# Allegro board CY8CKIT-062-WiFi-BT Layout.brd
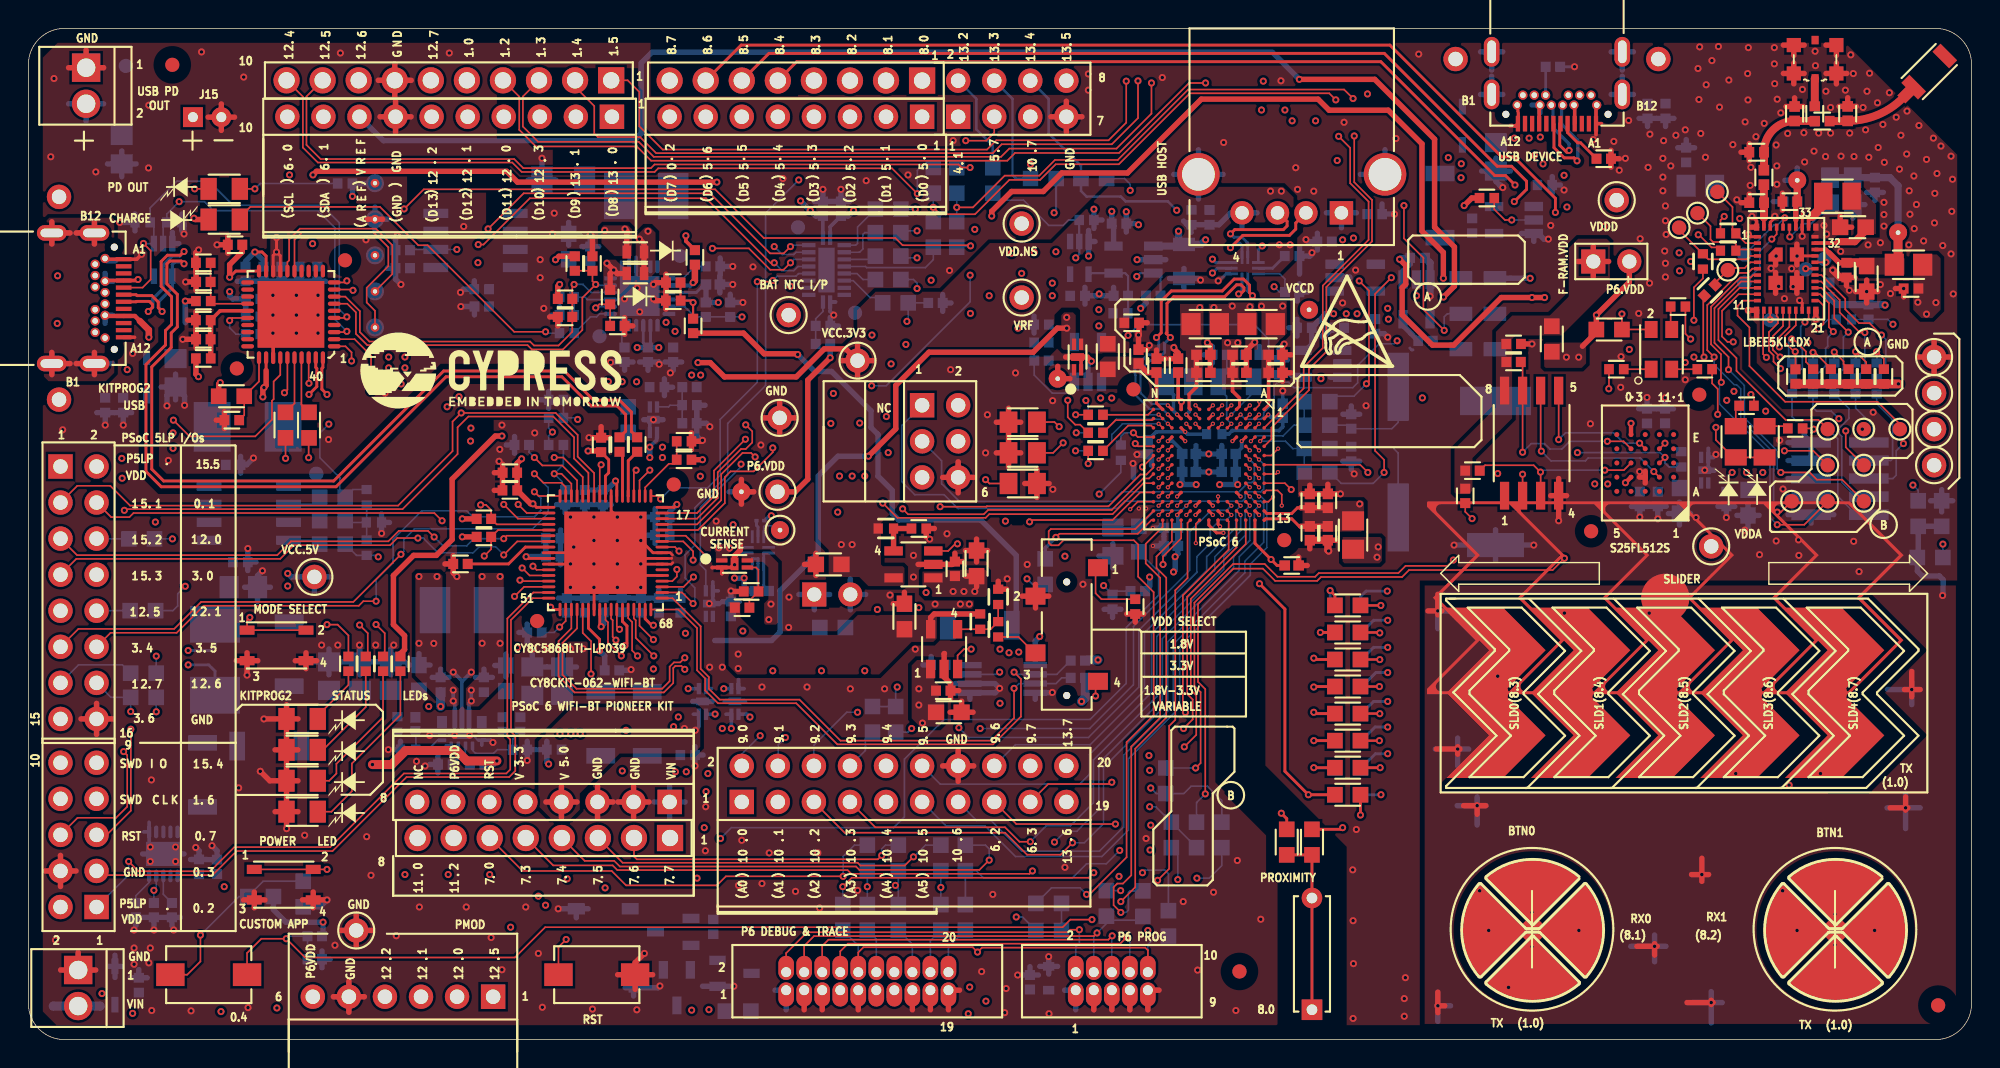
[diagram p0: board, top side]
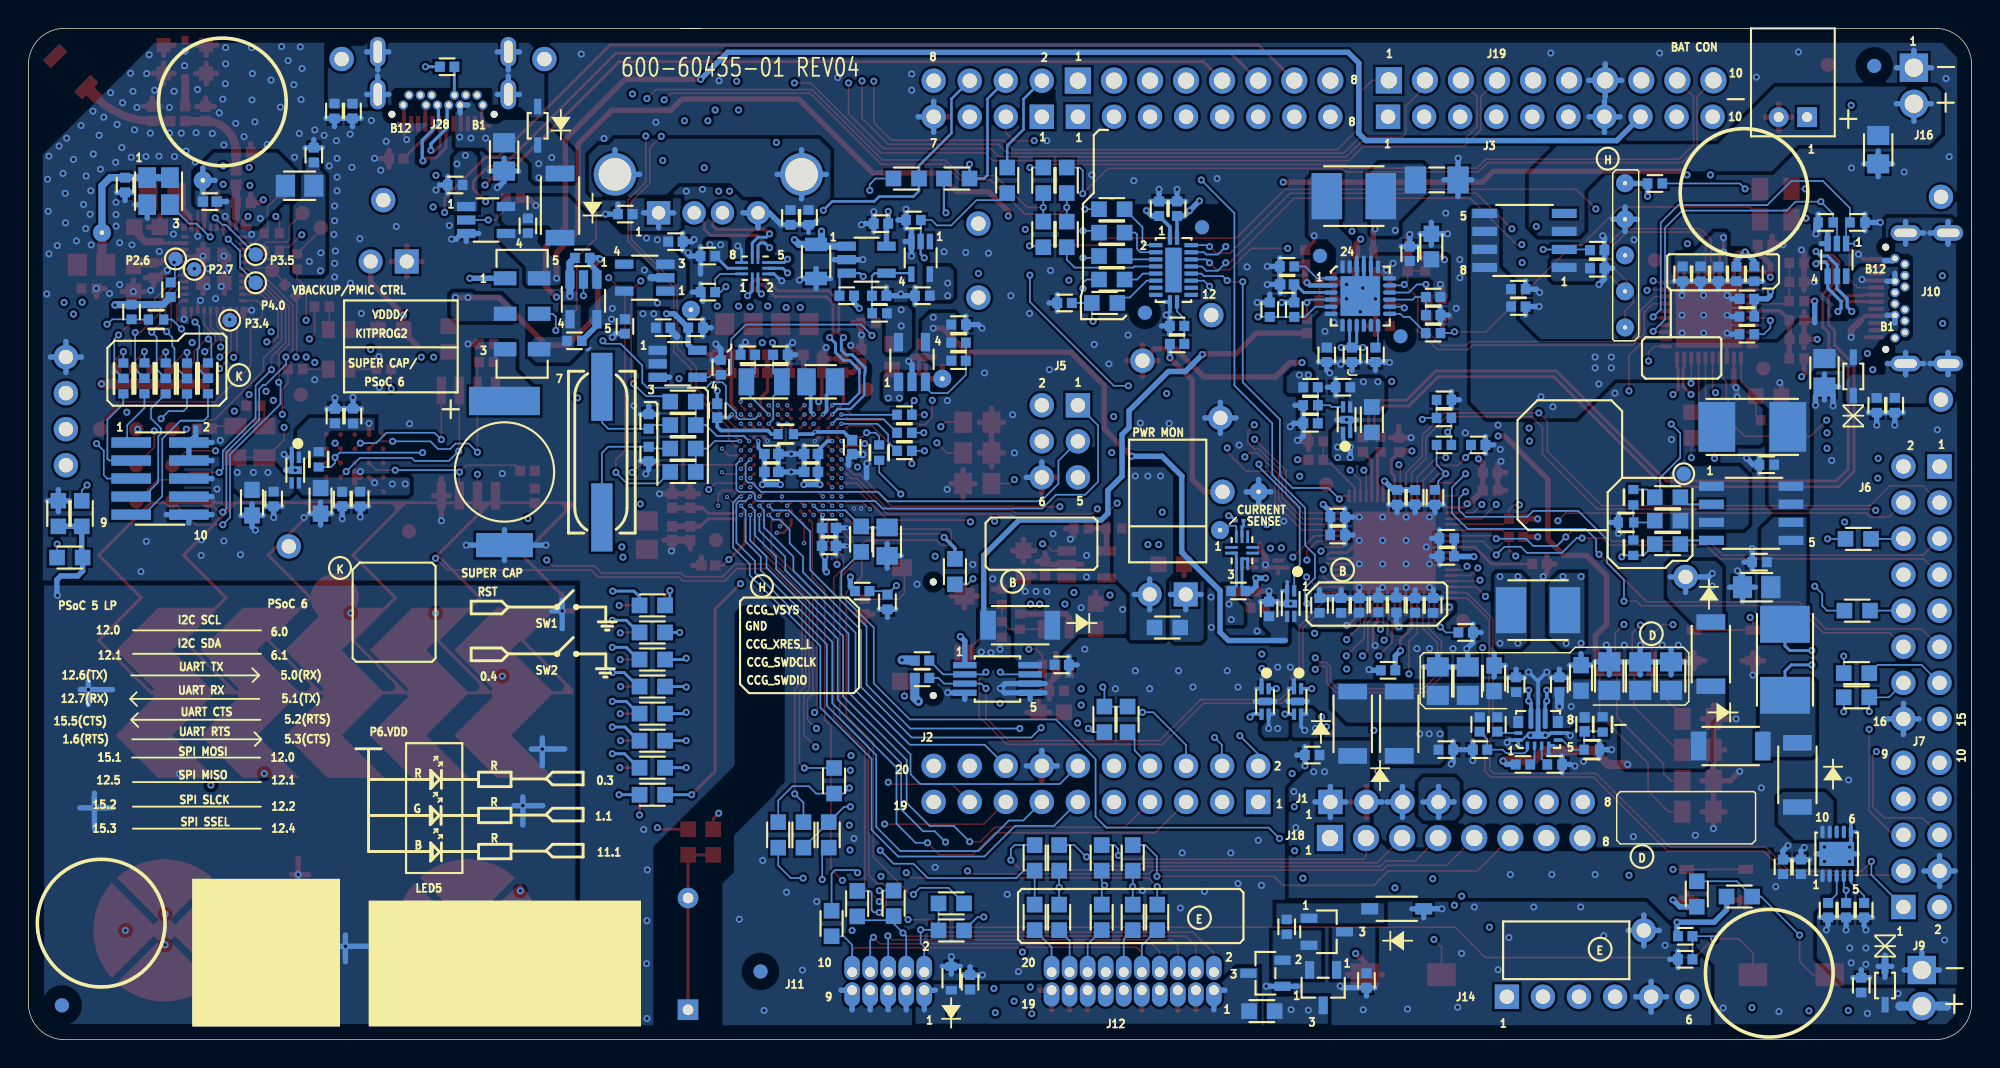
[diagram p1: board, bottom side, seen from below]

Outline 136.86 x 71.22 mm; copper layers: TOP, L02_GND, L03_SIG, L04_MIX, L05_MIX, L06_SIG, L07_GND, BOTTOM. Coordinates in mm from the lower left corner of the outline.
Outline path: 0,68.68 0,2.54 arc(0.74,0.74) 2.54,0 134.32,0 arc(136.11,0.74) 136.86,2.54 136.86,68.68 arc(136.11,70.48) 134.32,71.22 89.51,71.22 90.91,71.22 2.54,71.22 arc(0.74,70.48) 0,68.68

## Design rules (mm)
net group DP1: nets HOST_USB_DM HOST_USB_DP
net group DP2: nets DEV_USB_DM DEV_USB_DP
net group DP3: nets N17133557 N17133559
net group DP4: nets USB_DM USB_DP
net group P5LP_USB_D: nets P5LP_USB_DM P5LP_USB_DP
net group CL_CAPSEN: nets CAP_BUT0_P8_1 CAP_BUT1_P8_2 CAP_PROX_P8_0 CAP_SEG0_P8_3 CAP_SEG1_P8_4 CAP_SEG2_P8_5 CAP_SEG3_P8_6 CAP_SEG4_P8_7 CAP_TX_P1_0 J20_P8_1 J20_P8_2 J20_P8_3 J20_P8_4 J20_P8_5 J20_P8_6 J20_P8_7 P1_0 P8_1 P8_2 P8_3 P8_4 P8_5 P8_6 P8_7 P13_2 P13_3 P13_4
nets with their own width: min track width 0.559; nets ANT
nets with their own width: min track width 0.635; nets P5LP_VDD

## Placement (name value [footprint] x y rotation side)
ANT1  RFANT3216120A5T  [ANTENNA_RFANT3216120A5T]  133.87 68.18 45 top
C1  1.2 pF  [CAPC1005X61M]  128.13 65.22 270 top
C2  1.2 pF  [CAPC1005X61M]  124.39 65.21 270 top
C4  10pF  [CAPC1005X61M]  122.22 60.72 270 top
C5  0.1uF  [CAPC1005X55M_C]  124.05 59.02 180 top
C7  4.7uF  [CAPC1608X90M]  128.5 57.22 180 top
C8  1uF  [CAPC1005X55M_D]  14.55 55.98 180 top
C9  1uF  [CAPC1005X55M_D]  46.94 55.09 270 top
C10  0.1uF  [CAPC1005X55M_C]  12.32 54.71 180 top
C11  0.1uF  [CAPC1005X55M_C]  128.04 54.2 270 top
C12  4.7uF  [CAPC1608X90M]  129.46 53.59 270 top
C13  0.1uF  [CAPC1005X55M_C]  132.59 52.9 180 top
C14  0.1uF  [CAPC1005X55M_C]  45.42 52.04 180 top
C15  0.1uF  [CAPC1005X55M_C]  12.32 50.67 180 top
C16  0.1uF  [CAPC1005X55M_C]  77.7 50.49 180 top
C17  0.1uF  [CAPC1005X55M_C]  104.6 49 0 top
C18  0.1uF  [CAPC1005X55M]  82.75 48.23 0 top
C19  1uF  [CAPC1005X55M]  85.29 48.23 0 top
C20  0.1uF  [CAPC1005X55M]  87.83 48.23 0 top
C21  1uF  [CAPC1005X55M]  78.18 48.11 90 top
C22  0.1uF  [CAPC1005X55M]  79.45 47.47 90 top
C23  4.7uF  [CAPC1005X55M]  80.98 47.47 90 top
C24  10uF  [CAPC1005X55M]  82.75 46.96 0 top
C25  0.1uF  [CAPC1005X55M]  85.29 46.96 0 top
C26  1uF  [CAPC1005X55M]  87.83 46.96 0 top
C27  2.2nF  [CAPC2012X70M]  76.38 35.07 90 bottom
C28  0.1uF  [CAPC1005X55M_C]  14.33 43.63 180 top
C29  10nF  [CAPC2012X95M_A]  70.03 43.48 180 top
C30  1uF  [CAPC1005X55M_D]  40.34 41.88 270 top
C31  0.47nF  [CAPC2012X70M]  70.03 41.33 180 top
C32  1uF  [CAPC1005X55M_D]  33.91 39.93 180 top
C33  0.47nF  [CAPC2012X70M]  70.03 39.17 180 top
C34  0.1uF  [CAPC1005X55M_C]  33.91 38.68 180 top
C35  0.1uF  [CAPC1005X55M]  90.25 37.95 90 top
C36  1uF  [CAPC1005X55M]  91.52 37.95 90 top
C37  1uF  [CAPC1005X55M]  90.25 35.66 270 top
C38  0.1uF  [CAPC1005X55M]  91.52 35.66 270 top
C39  4.7uF  [CAPC1608X90M]  66.78 33.55 90 top
C40  1uF  [CAPC1005X55M_D]  30.43 33.5 180 top
C41  4.7uF  [CAPC1608X90M]  56.36 33.47 180 top
C42  1uF  [CAPC1005X55M]  88.97 33.39 0 top
C43  0.1uF  [CAPC1005X55M_D]  65.25 33.16 90 top
C44  0.1uF  [CAPC1005X55M_C]  50.9 31.56 0 top
C45  4.7uF  [CAPC1608X90M]  61.7 29.8 90 top
C46  0.1uF  [CAPC1005X55M_D]  64.43 24.58 0 top
C47  4.7uF  [CAPC1608X90M]  64.82 23.06 0 top
C48  10nF  [CAPC1005X55M_C]  114.03 65.41 270 bottom
C49  10uF  [CAPC2012X140M]  6.58 62.68 270 bottom
C50  0.1uF  [CAPC1005X55M_C]  116.75 62.3 90 bottom
C51  10uF  [CAPC2012X140M]  103.35 62.17 270 bottom
C52  22uF  [CAPC3216X180M_A]  37.67 60.55 180 bottom
C53  0.1uF  [CAPC1005X55M_C]  130.05 60.19 270 bottom
C54  2.2uF  [CAPC1005X55M]  124.08 59.02 180 bottom
C55  1uF  [CAPC1005X55M_D]  57.23 58.52 90 bottom
C56  1uF  [CAPC1005X55M_D]  55.96 58.52 270 bottom
C57  0.1uF  [CAPC1005X55M_C]  94.82 58.14 0 bottom
C58  10nF  [CAPC1005X55M_C]  83.18 57.91 270 bottom
C59  0.39nF  [CAPC1005X55M_B]  10.28 57.56 0 bottom
C60  0.39nF  [CAPC1005X55M_B]  8.04 57.56 180 bottom
C61  1uF  [CAPC1005X55M_D]  76.81 57.47 180 bottom
C62  1uF  [CAPC1005X55M_D]  91.29 56.2 0 bottom
C63  4.7uF  [CAPC1608X90M]  38.05 55.85 90 bottom
C64  0.1uF  [CAPC1005X55M_D]  39.57 55.35 90 bottom
C65  10nF  [CAPC1005X55M_C]  89 55.19 0 bottom
C66  10uF  [CAPC2012X100M]  81.38 54.81 270 bottom
C67  1uF  [CAPC1005X55M_D]  48.21 54.46 0 bottom
C68  0.1uF  [CAPC1005X55M_C]  20.35 53.93 270 bottom
C69  0.1uF  [CAPC1005X55M_C]  19.09 53.93 270 bottom
C70  1uF  [CAPC1005X55M_D]  17.83 53.93 270 bottom
C71  1uF  [CAPC1005X55M_D]  16.56 53.93 270 bottom
C72  0.1uF  [CAPC1005X55M_C]  15.3 53.93 270 bottom
C73  2.2uF  [CAPC1005X55M]  48.21 53.19 0 bottom
C74  10nF  [CAPC1005X55M_C]  31.92 52.86 0 bottom
C75  1uF  [CAPC1005X55M_D]  76.94 52.39 180 bottom
C76  0.1uF  [CAPC1005X55M_C]  73.89 52.39 180 bottom
C77  1uF  [CAPC1005X55M_D]  15.82 52.17 0 bottom
C78  1uF  [CAPC1005X55M_D]  31.92 51.64 0 bottom
C79  0.1uF  [CAPC1005X55M_C]  15.82 50.93 0 bottom
C80  0.1uF  [CAPC1005X55M_C]  71.35 50.36 0 bottom
C81  1uF  [CAPC1005X55M_D]  94.84 50.23 90 bottom
C82  0.1uF  [CAPC1005X55M_C]  89.87 50.14 0 bottom
C83  0.1uF  [CAPC1005X55M_C]  15.82 49.68 0 bottom
C84  0.1uF  [CAPC1005X55M_C]  71.35 49.09 0 bottom
C85  33pF  [CAPC1005X55M_D]  86.18 48.23 0 bottom
C86  18pF  [CAPC1005X55M_D]  83.9 48.23 180 bottom
C87  10uF  [CAPC1005X55M_D]  45.42 48.23 270 bottom
C88  1uF  [CAPC1005X55M_D]  43.64 48.23 270 bottom
C89  10uF  [CAPC2012X140M]  10.36 46.96 270 bottom
C90  0.1uF  [CAPC1005X55M_C]  44.27 45.95 180 bottom
C91  0.1uF  [CAPC1005X55M_C]  46.56 44.68 0 bottom
C92  10nF  [CAPC1005X55M_C]  5.41 44.68 270 bottom
C93  1uF  [CAPC1005X55M]  88.34 44.3 90 bottom
C94  1uF  [CAPC1005X55M_D]  115.27 43.92 90 bottom
C95  0.1uF  [CAPC1005X55M_C]  114 43.92 90 bottom
C96  12pF  [CAPC1005X55M_D]  93.17 43.54 90 bottom
C97  1uF  [CAPC1005X55M_D]  34.75 41.88 180 bottom
C98  4.7uF  [CAPC1005X55M]  78.84 41.72 270 bottom
C99  12pF  [CAPC1005X55M_D]  93.17 41.25 270 bottom
C100  1uF  [CAPC1005X55M]  84.53 41.25 180 bottom
C101  1uF  [CAPC1005X55M]  81.74 41.25 0 bottom
C102  0.1uF  [CAPC1005X55M_C]  14.43 40.49 180 bottom
C103  0.33F  [CAP_DSK-3R3H334T-HL]  103.33 39.98 180 bottom
C104  0.1uF  [CAPC1005X55M]  84.53 39.98 180 bottom
C105  0.1uF  [CAPC1005X55M]  81.74 39.98 0 bottom
C106  0.1uF  [CAPC1005X55M_C]  40.46 38.2 270 bottom
C107  1uF  [CAPC1005X55M_D]  39.19 38.2 270 bottom
C108  0.1uF  [CAPC1005X55M_C]  119.58 38.07 270 bottom
C109  1uF  [CAPC1005X55M_D]  114.76 38.07 270 bottom
C110  0.1uF  [CAPC1005X55M_C]  113.49 38.07 270 bottom
C111  22uF  [CAPC1608X90M]  116.28 37.95 270 bottom
C112  22uF  [CAPC1608X90M]  121.11 37.82 270 bottom
C113  1uF  [CAPC1005X55M_D]  44.65 36.8 180 bottom
C114  1uF  [CAPC1005X55M]  80.47 36.04 180 bottom
C115  0.1uF  [CAPC1005X55M_C]  44.65 35.53 180 bottom
C116  0.1uF  [CAPC1005X55M_C]  36.96 35.31 0 bottom
C117  0.1uF  [CAPC1005X55M]  80.47 34.77 180 bottom
C118  1uF  [CAPC1005X55M_D]  36.96 34.04 0 bottom
C119  0.1uF  [CAPC1005X55M_C]  14.94 33.63 180 bottom
C120  22uF  [CAPC2012X140M]  15.14 31.87 0 bottom
C121  0.1uF  [CAPC1005X55M_C]  76.35 30.83 270 bottom
C122  1uF  [CAPC1005X55M_D]  41.78 30.61 90 bottom
C123  0.1uF  [CAPC1005X55M_C]  40.51 30.61 90 bottom
C124  0.1uF  [CAPC1005X55M_C]  45.92 30.58 90 bottom
C125  0.1uF  [CAPC1005X55M_C]  44.4 30.58 90 bottom
C126  1uF  [CAPC1005X55M_D]  43.13 30.58 90 bottom
C127  1uF  [CAPC1005X55M_D]  39.19 30.58 90 bottom
C128  0.1uF  [CAPC1005X55M_C]  37.92 30.58 90 bottom
C129  0.1uF  [CAPC1005X55M_C]  49.48 30.33 90 bottom
C130  1uF  [CAPC1005X55M_D]  35.64 28.68 180 bottom
C131  0.1uF  [CAPC1005X55M_D]  64.08 26.39 180 bottom
C132  1uF  [CAPC1005X55M_D]  41.1 26.01 0 bottom
C133  22uF  [CAPC2012X140M]  25.52 25.6 90 bottom
C134  22uF  [CAPC2012X140M]  23.34 25.6 90 bottom
C135  22uF  [CAPC2012X140M]  21.17 25.6 90 bottom
C136  10uF  [CAPC1608X90M]  27.51 25.48 90 bottom
C137  10uF  [CAPC1608X90M]  33.63 25.45 90 bottom
C138  10uF  [CAPC2012X140M]  37.59 25.25 90 bottom
C139  10uF  [CAPC2012X140M]  35.48 25.25 90 bottom
C140  0.1uF  [CAPC1005X55M_C]  32.08 24.99 270 bottom
C141  0.1uF  [CAPC1005X55M_C]  29.03 24.99 270 bottom
C142  22pF  [CAPC1005X55M]  27.25 22.2 270 bottom
C143  0.1uF  [CAPC1005X55M_C]  29.36 19.38 0 bottom
C144  1uF  [CAPC1005X55M_D]  13.28 12.17 270 bottom
C145  10nF  [CAPC1005X55M_C]  12.01 12.17 270 bottom
C146  1uF  [CAPC1005X55M_D]  10.11 9.12 90 bottom
C147  1uF  [CAPC1005X55M_D]  70.54 4.04 90 bottom
C148  1uF  [CAPC1005X55M_C]  7.77 3.84 270 bottom
CAP_SH1  CAP_SHIELD  [CAP_SH1]  134.59 30.8 0 top
CSB1  Button 1  [CSB_10MM_3SEG]  105.94 7.7 270 top
CSB2  Button 2  [CSB_10MM_3SEG]  127.27 7.7 90 top
CSS1  Slider  [CSS_L5S_4X12_1P4_MUTUAL_CYPS]  115.28 24.42 0 top
D1  RB551SS-30T2R  [DIO160X80X63-2M]  42.75 55.47 180 top
D2  RB551SS-30T2R  [DIO160X80X63-2M]  42.75 53.95 180 top
D3  PMEG3020BEP  [SODFL4725X110M]  99.42 58.74 90 bottom
D4  PMEG3020BEP  [SODFL4725X110M]  67.01 29.18 0 bottom
D5  PMEG3020BEP  [SODFL4725X110M]  18.36 27.15 270 bottom
D6  PMEG3020BEP  [SODFL4725X110M]  40.31 22.25 270 bottom
D7  PMEG3020BEP  [SODFL4725X110M]  43.59 22.24 270 bottom
D8  PMEG3020BEP  [SODFL4725X110M]  16.97 20.68 0 bottom
D9  PMEG3020BEP  [SODFL4725X110M]  12.27 18.64 270 bottom
D10  BZT52C3V9-7-F  [SOD3715X145M]  40.49 9.21 0 bottom
J1  CON8  [SULLINS_PPPC081LFBN-RC]  45.16 16.74 180 top
J2  CON 10x2  [SULLINS_PPPC102LFBN-R_FLIP]  50.24 16.74 0 top
J3  CON10  [SULLINS_PPPC101LFBN-RC]  41.1 65 180 top
J4  CON8  [SULLINS_PPPC081LFBN-RC]  62.94 65 180 top
J5  HDR 3x2  [SULLINS_PPPC032LFBN-RC_FLIP]  62.94 44.68 270 top
J6  CON 8x2  [SULLINS_PPPC082LFBN-R_FLIP]  2.26 40.37 270 top
J7  CON 5x2  [SULLINS_PPPC052LFBN-RC_FLIP]  4.8 9.34 90 top
J8  2-pin R/A HDR  [HARWIN_M20-9960245]  55.35 31.35 0 bottom
J9  OSTVN02A150  [OST_OSTVN02A150]  3.51 4.9 270 top
J10  USB TYPE-C  [JAE_DX07S024XJ1R1100]  6.71 54.97 270 top
J11  HDR_S 5x2  [CNC_3220-10-0100-00]  73.76 3.48 0 top
J12  HDR_S 10x2  [CNCTECH_3220-20-0100-00]  53.37 3.48 0 top
J13  CON 2x1  [SAMTEC_BCS-101-L-S-HE]  90.4 2.1 0 top
J14  CON 6x1  [SULLINS_PPPC061LGBN-RC_FLIP]  32.73 3.02 0 top
J15  HDR_S 2x1_R/A  [JST_S2B-PH-K-S]  11.59 64.97 0 bottom
J16  OSTVN02A150  [OST_OSTVN02A150]  4.06 68.45 270 top
J18  HEADER 8  [SULLINS_PBC08SAAN]  45.19 14.2 180 top
J19  HEADER 10  [SULLINS_PBC10SAAN]  41.04 67.56 180 top
J20  HEADER 8  [SULLINS_PBC08SAAN]  62.94 67.55 180 top
J21  CON 4x2  [SULLINS_PPPC042LFBN-RC_FLIP]  65.48 67.54 0 top
J25  50MIL KEYED SMD  [SAMTEC_FTSH-105-01-L-DV-K]  129.62 42.05 270 bottom
J26  HDR 2x1  [3M_961102-6404-AR]  110.21 54.81 0 top
J27  0676433911  [MOLEX_676433911]  92.47 58.23 180 top
J28  DX07S024XJ1R1100  [JAE_DX07S024XJ1R1100]  110.4 64.51 180 top
J29  MM8430-2610RB3  [RF_SW_MUR_MM8430-2610B]  125.83 69.05 180 top
L1  6.8nH  [INDC1005X60M]  126.33 64.69 180 top
L2  2.2uH  [INDC2016X100M]  127.41 59.4 0 top
L3  1K @ 100MHz  [INDC2012X105M]  132.41 54.58 180 top
L4  1K @ 100MHz  [INDC2012X105M]  82.88 50.39 180 top
L5  1K @ 100MHz  [INDC2012X105M]  86.82 50.39 0 top
L6  1K @ 100MHz  [INDC2012X105M]  93.29 35.53 90 top
L7  1K @ 100MHz  [INDC2012X105M]  117.75 60.14 0 bottom
L8  1.5uH  [INDM4242X200M]  43.51 59.41 180 bottom
L9  2.2uH  [INDC2016X100M]  81.05 46.33 180 bottom
L10  1.5uH  [INDM4242X200M]  30.54 30.25 180 bottom
L11  6.8nH  [INDC1005X60M]  121.72 58.95 180 top
L12  6.8nH  [INDC1005X60M]  121.72 62.5 180 top
L13  6.8nH  [INDC1005X60M]  125.81 65.21 270 top
LED1  RED LED  [LEDC2012X120M]  19.28 18.23 180 top
LED2  AMBER LED  [LEDC2012X120M]  19.28 22.59 180 top
LED3  GREEN LED  [LEDC2012X120M]  19.28 20.41 180 top
LED4  AMBER LED  [LEDC2012X120M]  19.28 16.05 180 top
LED5  RGB LED  [LED_AAA3528LSEEZGKQBKS]  115.01 48.62 270 top
LED6  RED LED  [LEDC2012X120M]  13.79 57.76 0 top
LED7  GREEN LED  [LEDC2012X120M]  13.79 59.92 180 top
LED8  ORANGE LED  [LEDC2012X120M]  120.24 42.11 90 top
LED9  RED LED  [LEDC2012X120M]  122.28 42.11 90 top
NOREF  -  [unnamed]  2.16 45.08 0 top
NOREF#2  -  [#2]  140.67 111.58 0 top
NOREF#3  -  [#2]  -288.85 -207.67 0 top
NOREF#4  -  [unnamed#3]  10.13 68.66 0 top
NOREF#5  -  [unnamed#3]  85.29 4.8 0 top
NOREF#6  -  [unnamed]  114.79 69.06 270 top
NOREF#7  -  [unnamed#3]  134.5 2.41 0 top
NOREF#8  -  [#2]  0 4.22 0 top
NOREF#9  -  [#2]  130.83 0 90 top
NOREF#10  -  [#2]  39.6 25.37 0 top
NOREF#11  -  [#2]  39.6 23.73 0 top
NOREF#12  -  [unnamed]  100.51 69.06 270 top
NOREF#13  -  [#2]  5.28 0 90 top
NOREF#14  -  [#2]  122.89 73.48 0 top
NOREF#15  -  [#2]  135.98 0.62 0 top
NOREF#16  -  [#2]  0 66.56 0 top
NOREF#17  -  [#2]  32.43 47.14 0 top
NOREF#18  -  [unnamed]  2.16 59.36 0 top
NOREF#19  -  [#2]  17.48 -23.04 0 top
NOREF#20  -  [unnamed#3]  134.5 2.41 180 bottom
NOREF#21  -  [#2]  99.35 64.54 90 bottom
NOREF#22  -  [unnamed#3]  6.86 68.58 180 bottom
NOREF#23  -  [#2]  86.84 68.4 180 bottom
NOREF#24  -  [#2]  71.87 1.98 90 bottom
NOREF#25  -  [#2]  103.3 5.36 180 bottom
NOREF#26  -  [#2]  120.12 6.12 180 bottom
NOREF#27  -  [unnamed#3]  85.29 4.8 180 bottom
Q1  AO4838  [SOIC127P600X175-8M]  15.52 37.07 180 bottom
Q2  PMV48XP,215  [SOT95P230X110-3M]  45.42 7.59 270 bottom
Q3  DMP3098L-7  [SOT92P240X110-3M]  49.73 4.67 90 bottom
Q4  NTR4171PT1G  [SOT95P237X111-3M_A]  45.67 3.66 0 bottom
R1  10K  [RESC1005X40M_A]  38.48 54.66 90 top
R2  10K  [RESC1005X40M_A]  39.73 54.66 90 top
R3  75K  [RESC1005X40M_A]  12.32 53.36 0 top
R4  10K  [RESC1005X40M_A]  45.42 53.31 0 top
R5  10K  [RESC1005X40M_A]  40.97 52.3 90 top
R6  10K  [RESC1005X40M_A]  37.8 52.17 180 top
R7  120K  [RESC1005X40M_B]  12.32 52.02 0 top
R8  330ohm  [RESC1005X40M_B]  116.18 51.63 0 top
R9  10K  [RESC1005X40M_A]  37.8 50.9 180 top
R10  10K  [RESC1005X40M_A]  41.48 50.27 0 top
R11  10K  [RESC1005X40M_A]  46.81 50.27 90 top
R12  0ohm  [RESC1608X55M_A]  111.33 50.01 0 top
R13  0ohm  [RESC1608X55M_A]  107.29 49.34 90 top
R14  75K  [RESC1005X40M_A]  12.32 49.32 0 top
R15  0ohm  [RESC1608X55M_A]  76.02 48.11 270 top
R16  120K  [RESC1005X40M_B]  12.32 47.98 0 top
R17  10K  [RESC1005X40M_A]  104.6 47.73 180 top
R18  750ohm  [RESC1005X40M_B]  111.84 47.22 0 top
R19  270ohm  [RESC1005X40M_B]  118.06 47.22 0 top
R20  10K  [RESC1005X40M_A]  124.45 46.7 270 top
R21  49.9K  [RESC1005X40M_B]  125.7 46.7 90 top
R22  49.9K  [RESC1005X40M_B]  126.94 46.7 90 top
R23  49.9K  [RESC1005X40M_B]  128.19 46.7 90 top
R24  49.9K  [RESC1005X40M_B]  129.43 46.7 90 top
R25  49.9K  [RESC1005X40M_B]  130.68 46.7 90 top
R26  0ohm  [RESC1608X55M_A]  14.3 45.31 0 top
R27  1K  [RESC1005X40M_B]  121.01 44.65 180 top
R28  33OHM  [RESC1005X40M_B]  75.16 44.01 180 top
R29  0ohm  [RESC1608X55M_A]  18.11 43.28 90 top
R30  0ohm  [RESC1608X55M_A]  19.76 43.28 90 top
R31  100ohm  [RESC1005X40M_B]  124.43 43.05 180 top
R32  33OHM  [RESC1005X40M_B]  75.16 42.74 180 top
R33  30K  [RESC1005X40M_B]  46.18 42.14 180 top
R34  22ohm  [RESC1005X40M_A]  41.63 41.91 270 top
R35  22ohm  [RESC1005X40M_A]  42.88 41.91 270 top
R36  33OHM  [RESC1005X40M_B]  75.16 41.47 180 top
R37  15K  [RESC1005X40M_B]  46.18 40.84 180 top
R38  10K  [RESC1005X40M_A]  101.7 40.07 180 top
R39  10K  [RESC1005X40M_A]  101.19 38.3 270 top
R40  4.7K  [RESC1005X40M_A]  32.08 36.68 180 top
R41  158K  [RESC1005X40M]  60.39 36 180 top
R42  49.9K  [RESC1005X40M_B]  62.71 36 180 top
R43  4.7K  [RESC1005X40M_A]  32.08 35.41 180 top
R44  0ohm  [RESC1608X55M_A]  134.75 37.05 90 bottom
R45  0ohm  [RESC1608X55M_A]  133.1 37.05 90 bottom
R46  160K  [RESC1005X40M]  68.3 31.18 270 top
R47  560ohm  [RESC1608X55M_A]  92.91 30.58 180 top
R48  49.9K  [RESC1005X40M_B]  77.95 30.5 270 top
R49  10K  [RESC1005X40M_A]  50.27 30.42 0 top
R50  62K  [RESC1005X40M]  67.03 29.44 90 top
R51  22.6K  [RESC1005X40M]  68.3 28.9 90 top
R52  560ohm  [RESC1608X55M_A]  92.91 28.68 180 top
R53  560ohm  [RESC1608X55M_A]  92.91 26.77 180 top
R54  750ohm  [RESC1005X40M_B]  22.54 26.47 270 top
R55  750ohm  [RESC1005X40M_B]  23.76 26.47 270 top
R56  750ohm  [RESC1005X40M_B]  24.98 26.47 270 top
R57  390ohm  [RESC1005X40M_B]  26.2 26.47 270 top
R58  560ohm  [RESC1608X55M_A]  92.91 24.87 180 top
R59  560ohm  [RESC1608X55M_A]  92.91 22.96 180 top
R60  560ohm  [RESC1608X55M_A]  92.91 21.06 180 top
R61  560ohm  [RESC1608X55M_A]  92.91 19.15 180 top
R62  0ohm  [RESC1608X55M_A]  92.91 17.25 0 top
R63  560ohm  [RESC1608X55M_A]  88.62 13.91 90 top
R64  0ohm  [RESC1608X55M_A]  90.4 13.91 90 top
R65  0ohm  [RESC1608X55M_A]  19.35 10.25 270 bottom
R66  0ohm  [RESC1608X55M_A]  16.36 10.08 180 bottom
R67  10K  [RESC1005X40M_A]  20.17 7.28 0 bottom
R68  10K  [RESC1005X40M_A]  20.17 5.66 180 bottom
R69  100K  [RESC1005X40M_B]  115.3 65.41 270 bottom
R70  0ohm  [RESC1608X55M_A]  75.03 60.65 0 bottom
R71  0ohm  [RESC1608X55M_A]  71.48 60.65 0 bottom
R72  0ohm  [RESC1608X55M_A]  67.92 60.52 90 bottom
R73  0ohm  [RESC1608X55M_A]  65.38 60.52 90 bottom
R74  0ohm  [RESC1608X55M_A]  63.73 60.52 90 bottom
R75  750ohm  [RESC1005X40M_B]  22.3 60.3 180 bottom
R76  100K  [RESC1005X40M_B]  106.8 60.19 180 bottom
R77  0ohm  [RESC1608X55M_A]  60.55 58.49 180 bottom
R78  100K  [RESC1005X40M_B]  81.91 57.91 270 bottom
R79  100K  [RESC1005X40M_B]  74.52 57.73 0 bottom
R80  100K  [RESC1005X40M_B]  101.68 57.32 90 bottom
R81  0ohm  [RESC1608X55M_A]  60.55 56.84 180 bottom
R82  0ohm  [RESC1608X55M_A]  65.38 56.71 270 bottom
R83  0ohm  [RESC1608X55M_A]  63.73 56.71 270 bottom
R84  10K  [RESC1005X40M_A]  26.37 55.6 0 bottom
R85  0ohm  [RESC1608X55M_A]  60.55 55.19 180 bottom
R86  1M  [RESC1005X40M_B]  97.84 55.06 180 bottom
R87  150ohm  [RESC1005X40M_A]  26.37 54.33 180 bottom
R88  0ohm  [RESC1608X55M_A]  60.55 53.54 180 bottom
R89  10K  [RESC1005X40M_A]  126.84 52.82 270 bottom
R90  100K  [RESC1005X40M_A]  89 52.65 180 bottom
R91  10K  [RESC1005X40M_A]  79.22 52.39 0 bottom
R92  26.7K  [RESC1005X40M_A]  37.92 52.3 180 bottom
R93  0ohm  [RESC1608X55M_A]  61.06 51.88 180 bottom
R94  12.4K  [RESC1005X40M_A]  49.43 51.41 270 bottom
R95  10K  [RESC1005X40M_A]  47.7 51.41 90 bottom
R96  49.9K  [RESC1005X40M_B]  129.59 51.25 270 bottom
R97  100K  [RESC1005X40M_B]  76.91 51.16 0 bottom
R98  10K  [RESC1005X40M_A]  37.92 51.03 0 bottom
R99  0ohm  [RESC1005X40M]  127.86 50.72 180 bottom
R100  10K  [RESC1005X40M_A]  55.96 50.27 0 bottom
R101  100K  [RESC1005X40M_A]  92.15 50.14 0 bottom
R102  750ohm  [RESC1005X40M_B]  37.92 49.76 180 bottom
R103  100K  [RESC1005X40M_B]  98.4 49.22 180 bottom
R104  10K  [RESC1005X40M_A]  55.96 49 180 bottom
R105  400ohm  [RESC1005X40M_A]  41.99 48.23 270 bottom
R106  120K  [RESC1005X40M_A]  71.35 47.82 0 bottom
R107  100K  [RESC1005X40M_B]  88.09 47.35 90 bottom
R108  0ohm  [RESC1005X40M]  124.21 47.12 270 bottom
R109  0ohm  [RESC1005X40M]  128.68 47.12 270 bottom
R110  0ohm  [RESC1005X40M]  127.18 47.12 270 bottom
R111  0ohm  [RESC1005X40M]  130.17 47.11 270 bottom
R112  0ohm  [RESC1005X40M]  125.68 47.11 270 bottom
R113  0ohm  [RESC1005X40M]  124.21 46.03 270 bottom
R114  0ohm  [RESC1005X40M]  128.68 46.03 270 bottom
R115  0ohm  [RESC1005X40M]  127.18 46.02 270 bottom
R116  0ohm  [RESC1005X40M]  130.17 46.02 270 bottom
R117  0ohm  [RESC1005X40M]  125.68 46.02 270 bottom
R118  120K  [RESC1005X40M_A]  46.56 45.95 180 bottom
R119  49.9K  [RESC1005X40M_B]  37.16 45.06 0 bottom
R120  0ohm  [RESC1608X55M_A]  90.75 44.93 0 bottom
R121  100K  [RESC1005X40M_B]  6.68 44.68 270 bottom
R122  33OHM  [RESC1005X40M_B]  75.16 44.01 180 bottom
R123  49.9K  [RESC1005X40M_B]  37.16 43.79 180 bottom
R124  0ohm  [RESC1608X55M_A]  42.24 43.66 270 bottom
R125  75K  [RESC1005X40M_A]  46.56 43.41 180 bottom
R126  0ohm  [RESC1608X55M_A]  90.75 43.28 0 bottom
R127  200ohm  [RESC6432X120M]  15.44 43.15 0 bottom
R128  33OHM  [RESC1005X40M_B]  75.16 42.74 180 bottom
R129  0ohm  [RESC1005X40M]  83.52 42.65 0 bottom
R130  15K  [RESC1005X40M_B]  37.16 41.88 0 bottom
R131  0ohm  [RESC1608X55M_A]  90.75 41.63 0 bottom
R132  33OHM  [RESC1005X40M_B]  75.16 41.47 180 bottom
R133  0ohm  [RESC1005X40M]  76.94 41.34 90 bottom
R134  10K  [RESC1005X40M]  116.41 40.87 270 bottom
R135  0ohm  [RESC1608X55M_A]  90.75 39.98 0 bottom
R136  30K  [RESC1005X40M_B]  37.8 38.2 90 bottom
R137  10M  [RESC1005X40M]  23.83 38.2 270 bottom
R138  0ohm  [RESC1608X55M_A]  21.41 38.2 180 bottom
R139  0ohm  [RESC1608X55M_A]  21.41 36.55 180 bottom
R140  0ohm  [RESC1005X40M]  24.33 36.42 180 bottom
R141  0ohm  [RESC1608X55M_A]  7.98 35.27 0 bottom
R142  0ohm  [RESC1608X55M_A]  78.21 35.25 270 bottom
R143  0ohm  [RESC1608X55M_A]  21.41 34.9 180 bottom
R144  10M  [RESC1005X40M]  23.83 34.65 270 bottom
R145  0ohm  [RESC1608X55M_A]  133.93 33.95 0 bottom
R146  0ohm  [RESC1608X55M_A]  71.6 32.96 90 bottom
R147  4.7K  [RESC1005X40M_A]  78.13 31.59 180 bottom
R148  200mOHM  [RESC1005X40M_A]  51.64 31.6 0 bottom
R149  0ohm  [RESC1608X55M_A]  92.91 30.58 0 bottom
R150  0ohm  [RESC1608X55M_A]  8.06 30.21 0 bottom
R151  0ohm  [RESC1608X55M_A]  56.64 29.02 0 bottom
R152  0ohm  [RESC1608X55M_A]  92.91 28.68 0 bottom
R153  0ohm  [RESC1608X55M_A]  92.91 26.77 0 bottom
R154  0.01R  [RESC6432X120M]  13.14 26.75 90 bottom
R155  4.7K  [RESC1005X40M_A]  73.91 26.7 180 bottom
R156  0ohm  [RESC1608X55M_A]  8.1 25.81 0 bottom
R157  4.7K  [RESC1005X40M_A]  73.91 25.48 180 bottom
R158  0ohm  [RESC1608X55M_A]  92.91 24.87 0 bottom
R159  0ohm  [RESC1608X55M_A]  8.1 24.11 0 bottom
R160  0ohm  [RESC1608X55M_A]  92.91 22.96 0 bottom
R161  0ohm  [RESC1608X55M_A]  61.08 22.56 270 bottom
R162  0ohm  [RESC1608X55M_A]  59.44 22.56 270 bottom
R163  10K  [RESC1005X40M_A]  34.65 22.2 90 bottom
R164  10K  [RESC1005X40M_A]  33.4 22.2 90 bottom
R165  560K  [RESC1005X40M]  25.98 22.2 90 bottom
R166  0ohm  [RESC1608X55M_A]  92.91 21.06 0 bottom
R167  100K  [RESC1005X40M_B]  37.03 20.42 0 bottom
R168  10K  [RESC1005X40M_A]  34.62 20.42 180 bottom
R169  100K  [RESC1005X40M]  26.75 20.42 0 bottom
R170  100K  [RESC1005X40M_B]  46.43 20.04 180 bottom
R171  100K  [RESC1005X40M_A]  31.6 19.38 180 bottom
R172  0ohm  [RESC1608X55M_A]  92.91 19.15 0 bottom
R173  0ohm  [RESC1608X55M_A]  80.11 18.23 90 bottom
R174  0ohm  [RESC1608X55M_A]  92.91 17.25 0 bottom
R175  0ohm  [RESC1608X55M_A]  84.05 14.42 270 bottom
R176  0ohm  [RESC1608X55M_A]  82.27 14.42 90 bottom
R177  0ohm  [RESC1608X55M_A]  80.49 14.42 270 bottom
R178  0ohm  [RESC1608X55M_A]  65.99 12.8 90 bottom
R179  0ohm  [RESC1608X55M_A]  64.26 12.8 90 bottom
R180  0ohm  [RESC1608X55M_A]  61.27 12.8 90 bottom
R181  0ohm  [RESC1608X55M_A]  59.08 12.8 90 bottom
R182  0ohm  [RESC1608X55M_A]  80.29 8.18 90 bottom
R183  0ohm  [RESC1608X55M_A]  75.92 9.59 90 bottom
R184  10K  [RESC1005X40M_A]  8.84 9.12 90 bottom
R185  4.7K  [RESC1005X40M_A]  7.57 9.12 90 bottom
R186  0ohm  [RESC1608X55M_A]  65.99 8.61 270 bottom
R187  0ohm  [RESC1608X55M_A]  64.26 8.61 270 bottom
R188  0ohm  [RESC1608X55M_A]  61.27 8.61 270 bottom
R189  0ohm  [RESC1608X55M_A]  59.08 8.61 270 bottom
R190  0ohm  [RESC1608X55M_A]  57.35 8.61 270 bottom
R191  0ohm  [RESC1608X55M_A]  78.49 9.58 270 bottom
R192  0ohm  [RESC1608X55M_A]  71.86 9.59 0 bottom
R193  15K  [RESC1005X40M_B]  48.23 7.94 90 bottom
R194  0ohm  [RESC1608X55M_A]  71.86 7.69 180 bottom
R195  10K  [RESC1005X40M_A]  42.62 4.17 90 bottom
R196  0ohm  [RESC1608X55M_A]  49.99 2.01 180 bottom
R197  100K  [RESC1005X40M_B]  102.72 59.28 180 top
R198  4.7K  [RESC1005X40M_A]  110.95 62.04 180 top
R199  4.7K  [RESC1005X40M_A]  107.37 68.52 180 bottom
R200  0ohm  [RESC1005X40M]  119.71 56.79 0 top
R201  0ohm  [RESC1005X40M]  119.71 55.57 0 top
R202  0ohm  [RESC1005X40M]  117.93 54.81 90 top
R203  0ohm  [RESC1005X40M]  118.41 52.77 45 top
R204  10K  [RESC1005X40M_A]  63.88 51.88 180 bottom
SH1  Short  [NET_TIE_COPPERTRACE]  51.55 36.55 0 bottom
SW1  EVQ-PE105K  [SW_EVQ-PE105K]  40.03 4.57 180 top
SW2  EVQ-PE105K  [SW_EVQ-PE105K]  12.7 4.57 0 top
SW3  SKRPACE010  [SW_SKRPACE010]  17.48 27.76 0 top
SW4  SKRPACE010  [SW_SKRPACE010]  17.98 10.91 0 top
SW5  CL-SB-13B-01T  [SW_CL-SB-13B-01T]  73.13 29.24 270 top
SW7  JS202011JCQN  [SW_JS202011JCQN]  102.08 51.12 270 bottom
TP1  TP_SMD  [TP127D033]  124.57 60.52 0 top
TP2  RED  [KEYSTONE_5000]  111.86 59.12 0 top
TP3  RED  [KEYSTONE_5000]  69.95 57.47 0 top
TP4  TP_SMD  [TP127D033]  131.68 56.84 0 top
TP5  RED  [KEYSTONE_5000]  69.95 52.27 0 top
TP6  TP_SMD  [TP127D033]  90.2 51.4 0 top
TP7  RED  [KEYSTONE_5000]  53.54 51.03 0 top
TP8  BLACK  [KEYSTONE_5000]  134.21 48.07 0 top
TP9  RED  [KEYSTONE_5000]  58.39 47.82 0 top
TP10  TP_SMD  [TP127D033]  72.49 46.55 0 top
TP11  RED  [KEYSTONE_5000]  134.21 45.53 0 top
TP12  BLACK  [KEYSTONE_5000]  52.91 43.79 0 top
TP13  TP_SMD  [TP102C]  126.72 42.99 0 top
TP14  TP_SMD  [TP102C]  129.26 42.99 0 top
TP15  TP_SMD  [TP102C]  131.8 42.99 0 top
TP16  RED  [KEYSTONE_5000]  134.21 42.99 0 top
TP17  TP_SMD  [TP102C]  126.72 40.45 0 top
TP18  TP_SMD  [TP102C]  129.26 40.45 0 top
TP19  RED  [KEYSTONE_5000]  134.21 40.45 0 top
TP20  TP_SMD  [TP127D033]  50.22 38.58 0 top
TP21  RED  [KEYSTONE_5000]  52.76 38.58 0 top
TP22  TP_SMD  [TP102C]  124.18 37.91 0 top
TP23  TP_SMD  [TP102C]  126.72 37.91 0 top
TP24  TP_SMD  [TP102C]  129.26 37.91 0 top
TP25  TP_SMD  [TP127D033]  52.93 35.88 0 top
TP26  RED  [KEYSTONE_5000]  118.52 34.74 0 top
TP27  RED  [KEYSTONE_5000]  20.14 32.59 0 top
TP28  BLACK  [KEYSTONE_5000]  23.09 7.69 0 top
TP29  TP_SMD  [TP50_12D_24BOT_MIL]  24.41 60.32 270 bottom
TP30  TP_SMD  [TP50_12D_24BOT_MIL]  24.41 57.78 270 bottom
TP31  TP_SMD  [TP102C]  120.85 55.29 180 bottom
TP32  TP_SMD  [TP50_12D_24BOT_MIL]  24.41 55.24 270 bottom
TP33  TP_SMD  [TP102C]  126.49 54.98 180 bottom
TP34  TP_SMD  [TP102C]  125.17 54.25 180 bottom
TP35  TP_SMD  [TP102C]  120.85 53.31 180 bottom
TP36  TP_SMD  [TP50_12D_24BOT_MIL]  24.41 52.7 270 bottom
TP37  TP_SMD  [TP102C]  122.68 50.67 180 bottom
TP38  TP_SMD  [TP50_12D_24BOT_MIL]  24.41 50.16 270 bottom
TP39  TP_SMD  [TP102C]  20.27 39.85 180 bottom
TP40  TP_SMD  [TP102C]  118.95 59.71 0 top
TP41  TP_SMD  [TP102C]  117.55 58.21 0 top
TP42  TP_SMD  [TP102C]  116.26 57.19 0 top
TP43  TP_SMD  [TP102C]  119.68 54.2 0 top
TVS1  SD05-7  [SOD2513X120M_DI]  100.99 64.36 90 bottom
TVS2  DT2636-04S-7  [SOT65P210X110-6M]  9.49 54.91 270 bottom
TVS3  SD12CT1G  [SOD2513X120M_12_DI]  8.33 46.71 90 bottom
TVS4  ESD3V3D5-TP  [SODFL1608X77M]  71.86 4.32 270 bottom
TVS5  SD12CT1G  [SOD2513X120M_12_DI]  6.1 3.81 270 bottom
U1  CY8C6247BZI-D54  [BGA124C65P13X13_900X900X100]  83.13 40.49 270 top
U2  CY8C5868LTI-LP039  [QFN40P800X800X100-69M]  40.64 34.29 180 top
U3  CYPD3125-40LQXIES  [QFN50P600X600X60-41M]  18.49 51.08 180 top
U4  S25FL512SAGBHIA10  [BGA24C100P5X5_600X800X120]  113.87 40.61 180 top
U5  FM25V10  [SOIC127P800X203-8M]  105.87 42.01 90 top
U6  LBEE5KL1DX-TEMP  [MODULE_LBEE5KL1DX-TEMP]  123.8 54.3 0 top
U7  SIP32401ADNP  [TDFN50P160X120X60-5M]  73.89 48.07 90 top
U8  SiP32408  [TDFN50P160X120X60-5M]  49.73 33.5 0 top
U9  AP7365-WG-7  [SOT95P285X140-5M]  62.33 33.47 180 top
U10  AP7365-WG-7  [SOT95P285X140-5M]  64.49 27.5 90 top
U11  ASDK-32.768KHZ-LRT  [OSCCC200X250X90-4M]  127.69 59.76 270 bottom
U12  74LVCE1G126W5-7  [SOT95P280X145-5M]  104.62 57.73 180 bottom
U13  BTS4175SGA  [SOIC127P600X175-8M]  31.49 56.29 0 bottom
U14  74LVC1G07GW,125  [TSSOP65P212X110-5M]  74.02 55.06 270 bottom
U15  AP2151WG-7  [SOT95P285X140-5M]  77.83 54.93 180 bottom
U16  NLAS7242MUTBG  [QFN40P140X180X60-10M]  85.67 54.33 90 bottom
U17  FXMA108BQX  [DQFN50P250X450X80-21M]  56.21 54.2 180 bottom
U18  TCR2EF18,LM(CT  [SOT95P275X140-5M]  93.45 53.66 0 bottom
U19  BQ24266RGER  [QFN50P400X400X100-25M]  43.06 52.37 180 bottom
U20  74LVCE1G126W5-7  [SOT95P280X145-5M]  97.76 52.14 270 bottom
U21  LMV321ILT  [SOT95P280X145-5M]  74.63 47.73 90 bottom
U22  74LVCE1G126W5-7  [SOT95P280X145-5M]  91.14 47.6 180 bottom
U23  SIP32401ADNP  [TDFN50P160X120X60-5M]  44.02 43.66 90 bottom
U24  SIP32402ADNP  [TDFN50P160X120X60-5M]  118.06 40.11 270 bottom
U25  INA216A3RSW  [QFN40P140X180X55-10M]  51.38 34.47 270 bottom
U26  SIP32402ADNP  [TDFN50P160X120X60-5M]  47.96 30.71 270 bottom
U27  ISL95810UIU8Z-T  [MSOP65P490X110-8M]  68.61 25.4 180 bottom
U28  SiP32408  [TDFN50P160X120X60-5M]  49.76 23.82 270 bottom
U29  SiP32408  [TDFN50P160X120X60-5M]  47.47 23.82 270 bottom
U30  TPS63070  [QFN50P250X300X100-15M_NOFID]  30.53 21.84 90 bottom
U31  SiP32429  [SON50P300X300X100-11M_VS]  9.5 13.08 90 bottom
Y1  32.768KHz  [XTAL320X150X90N_ECS]  85.04 46.33 0 bottom
Y2  17.2032MHz  [XTL-11-5X4-8MM_DAB]  96.47 41.38 90 bottom

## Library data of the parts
ANT1 = Wiggle Antenna_7
C1 C2 C4 C7 C12 C27 C29 C31 C33 C96 C99 = CAP
C5 C8-C11 C13-C26 C28 C30 C32 C34-C54 C57-C84 C87-C95 C97 C98 C100-C102 C104-C148 = CAPACITOR NON-POL
C55 C56 C85 C86 = CAP NP
C103 = CAP POL
CAP_SH1 = CAP_SHIELD
CSB1 CSB2 = Cap_Button_Circle_Mutual
CSS1 = CapSense Slider 5 Seg Mutual_2
D1-D9 = DIO STKY PMEG3020_0
D10 = DIODE ZENER_2
J1 J4 = CON8
J2 = CONN_8
J3 = CON10
J5 = RECPT 4X2 100MIL_3
J6 = CONN_7
J7 = RECPT 4X2 100MIL_5
J8 J26 = 2 PIN Header
J9 J16 = Terminal_Block
J10 J28 = CONN_USB_TYPE_C
J11 J25 = RECPT 4X2 100MIL_2
J12 = 20-pin connector
J13 = TEST POINT_0
J14 = CON6_0
J15 = CONN FLEX 2
J18 J20 = HEADER 8
J19 = HEADER 10
J21 = RECPT 4X2 100MIL_6
J27 = USB_A_RECEPTACLE
J29 = CONN_MMCX_0
L1 L2 L8 L9 L11-L13 = INDUCTOR
L3-L7 = INDUCTOR FERRITE
L10 = INDUCTOR: room: room1
LED1-LED4 LED6-LED9 = LED_0
LED5 = RGB_LED
Q1 = MOSFET_N_GDS_10
Q2 Q4 = P DGS_5
Q3 = P DGS_4
R1-R43 R46-R64 R67-R126 R128-R136 R138-R143 R146 R147 R149-R162 R166 R167 R170 R172-R195 R197-R204 = RESISTOR
R44 R45 R65 R66 R145 R148 R196 = 330 ohm 5% 0805_0
R127 = 100-16W-1%-2512
R137 R144 = R
R163-R165 R168 R169 R171 = RESISTOR: room: room1
SH1 = Short_2
SW1 SW2 = SW KEY-SPST_1
SW3 SW4 = SW PUSH NO 4-PIN
SW5 = SW_SP3T
SW7 = SW_DPDT_JS202011CQN_1
TP1-TP43 = TEST_POINT
TVS1 TVS4 = TVS 5V SOD-323_0
TVS2 = DT2636-04S-7
TVS3 TVS5 = DIODE BI-DIR TRIG
U1 = PSoC6_BLE_Hetero_0
U2 = CY8C38***-QFN68_1
U3 = CYPD3125-40LQXIES_3
U4 = S25FL512SAGBHIA13_1
U5 = ULE_FRAM
U6 = CYPD2122-24LQXIT_6
U7 U23 U24 U26 = SIP32402ADNP_1
U8 U28 U29 = SiP32408_0
U9 U10 = AP7365-WG-7
U11 = SG-210STF 32.7680ML
U12 U20 = AP22802_5
U13 = BTS4175SGA
U14 = 74LVC1G07
U15 = AP22802
U16 = NLAS7242
U17 = FXMA108_0
U18 = AP22802_3
U19 = BQ24266RGER_4
U21 = OP-07_4
U22 = AP22802_2
U25 = INA216A3RSW_2
U27 = ISL95810UIU8Z-T
U30 = TPS63000_3: room: room1
U31 = SiP32429_1
Y1 Y2 = CRYSTAL

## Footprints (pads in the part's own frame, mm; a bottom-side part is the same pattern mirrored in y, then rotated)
3M_961102-6404-AR
  rect 1.7x1.7 hole 1: 1(0,0)
  round 1.7 hole 1: 2(2.54,0)
ANTENNA_RFANT3216120A5T
  custom 0.408x0.408 smd: 1(-1.965,0)
  rect 0.8x1.66 smd: 2(1.55,0)
BGA24C100P5X5_600X800X120
  round 1 smd: (-3.809,-4.809) (3.809,4.809)
  round 0.35 smd: A2(-1,2) A3(0,2) A4(1,2) A5(2,2) B1(-2,1) B2(-1,1) B3(0,1) B4(1,1) B5(2,1) C1(-2,0) C2(-1,0) C3(0,0) C4(1,0) C5(2,0) D1(-2,-1) D2(-1,-1) D3(0,-1) D4(1,-1) D5(2,-1) E1(-2,-2) E2(-1,-2) E3(0,-2) E4(1,-2) E5(2,-2)
BGA124C65P13X13_900X900X100
  round 1 smd: (-5.31,-5.31) (5.31,5.31)
  round 0.25 smd: A1(-3.9,3.9) A2(-3.25,3.9) A3(-2.6,3.9) A4(-1.95,3.9) A5(-1.3,3.9) A6(-0.65,3.9) A7(0,3.9) A8(0.65,3.9) A9(1.3,3.9) A10(1.95,3.9) A11(2.6,3.9) A12(3.25,3.9) A13(3.9,3.9) B1(-3.9,3.25) B2(-3.25,3.25) B3(-2.6,3.25) B4(-1.95,3.25) B5(-1.3,3.25) B6(-0.65,3.25) B7(0,3.25) B8(0.65,3.25) B9(1.3,3.25) B10(1.95,3.25) B11(2.6,3.25) B12(3.25,3.25) B13(3.9,3.25) C1(-3.9,2.6) C2(-3.25,2.6) C3(-2.6,2.6) C4(-1.95,2.6) C5(-1.3,2.6) C6(-0.65,2.6) C7(0,2.6) C8(0.65,2.6) C9(1.3,2.6) C10(1.95,2.6) C11(2.6,2.6) C12(3.25,2.6) C13(3.9,2.6) D1(-3.9,1.95) D2(-3.25,1.95) D3(-2.6,1.95) D4(-1.95,1.95) D10(1.95,1.95) D11(2.6,1.95) D12(3.25,1.95) D13(3.9,1.95) E1(-3.9,1.3) E2(-3.25,1.3) E3(-2.6,1.3) E11(2.6,1.3) E12(3.25,1.3) E13(3.9,1.3) F1(-3.9,0.65) F2(-3.25,0.65) F3(-2.6,0.65) F11(2.6,0.65) F12(3.25,0.65) F13(3.9,0.65) G1(-3.9,0) G2(-3.25,0) G3(-2.6,0) G11(2.6,0) G12(3.25,0) G13(3.9,0) H1(-3.9,-0.65) H2(-3.25,-0.65) H3(-2.6,-0.65) H11(2.6,-0.65) H12(3.25,-0.65) H13(3.9,-0.65) J1(-3.9,-1.3) J2(-3.25,-1.3) J3(-2.6,-1.3) J11(2.6,-1.3) J12(3.25,-1.3) J13(3.9,-1.3) K1(-3.9,-1.95) K2(-3.25,-1.95) K3(-2.6,-1.95) K4(-1.95,-1.95) K10(1.95,-1.95) K11(2.6,-1.95) K12(3.25,-1.95) K13(3.9,-1.95) L1(-3.9,-2.6) L2(-3.25,-2.6) L3(-2.6,-2.6) L4(-1.95,-2.6) L5(-1.3,-2.6) L6(-0.65,-2.6) L7(0,-2.6) L8(0.65,-2.6) L9(1.3,-2.6) L10(1.95,-2.6) L11(2.6,-2.6) L12(3.25,-2.6) L13(3.9,-2.6) M1(-3.9,-3.25) M2(-3.25,-3.25) M3(-2.6,-3.25) M4(-1.95,-3.25) M5(-1.3,-3.25) M6(-0.65,-3.25) M7(0,-3.25) M8(0.65,-3.25) M9(1.3,-3.25) M10(1.95,-3.25) M11(2.6,-3.25) M12(3.25,-3.25) M13(3.9,-3.25) N1(-3.9,-3.9) N2(-3.25,-3.9) N3(-2.6,-3.9) N4(-1.95,-3.9) N5(-1.3,-3.9) N6(-0.65,-3.9) N7(0,-3.9) N8(0.65,-3.9) N9(1.3,-3.9) N10(1.95,-3.9) N11(2.6,-3.9) N12(3.25,-3.9) N13(3.9,-3.9)
CAP_DSK-3R3H334T-HL
  rect 5x2 smd: 1(0,5)
  rect 4x1.7 smd: 2(0,-5.15)
CAP_SH1
  rect 0.3x0.25 smd: 1(0.203,0.465)
CAPC1005X55M
  rect 0.75x0.72 smd: 1(-0.49,0) 2(0.49,0)
CAPC1005X55M_B
  rect 0.67x0.72 smd: 1(-0.53,0) 2(0.53,0)
CAPC1005X55M_C
  rect 0.69x0.72 smd: 1(-0.52,0) 2(0.52,0)
CAPC1005X55M_D
  rect 0.7x0.72 smd: 1(-0.51,0) 2(0.51,0)
CAPC1005X61M
  rect 0.75x0.75 smd: 1(-0.51,0) 2(0.51,0)
CAPC1608X90M
  rect 1.15x1.1 smd: 1(-0.9,0) 2(0.9,0)
CAPC2012X70M
  rect 1.25x1.5 smd: 1(-1,0) 2(1,0)
CAPC2012X95M_A
  rect 1.25x1.5 smd: 1(-1,0) 2(1,0)
CAPC2012X100M
  rect 0.95x1.55 smd: 1(-1.2,0) 2(1.2,0)
CAPC2012X140M
  rect 1.35x1.55 smd: 1(-1,0) 2(1,0)
CAPC3216X180M_A
  rect 1.5x1.9 smd: 1(-1.5,0) 2(1.5,0)
CNC_3220-10-0100-00
  oval 1.1x1.7 hole 0.7: 1(0,0) 2(0,1.27) 3(1.27,0) 4(1.27,1.27) 5(2.54,0) 6(2.54,1.27) 7(3.81,0) 8(3.81,1.27) 9(5.08,0) 10(5.08,1.27)
CNCTECH_3220-20-0100-00
  oval 1.1x1.7 hole 0.7: 1(0,0) 2(0,1.27) 3(1.27,0) 4(1.27,1.27) 5(2.54,0) 6(2.54,1.27) 7(3.81,0) 8(3.81,1.27) 9(5.08,0) 10(5.08,1.27) 11(6.35,0) 12(6.35,1.27) 13(7.62,0) 14(7.62,1.27) 15(8.89,0) 16(8.89,1.27) 17(10.16,0) 18(10.16,1.27) 19(11.43,0) 20(11.43,1.27)
CSB_10MM_3SEG
  custom 1.151x1.151 smd: 1(-2.697,0) 2(2.697,0)
  custom 1.654x1.654 smd: 3(0,0)
CSS_L5S_4X12_1P4_MUTUAL_CYPS
  custom 1.75x1.75 smd: 1(-11.925,0) 2(-5.961,0) 3(0,0) 4(5.961,0) 5(11.925,0)
  custom 3.398x3.398 smd: 6(0,6.692)
DIO160X80X63-2M
  rect 0.6x0.92 smd: A(0.61,0) K(-0.61,0)
DQFN50P250X450X80-21M
  round 1 smd: (-2.009,-3.009) (2.009,3.009)
  rect 0.3x0.95 smd: 1(-0.25,2.25) 10(-0.25,-2.25) 11(0.25,-2.25) 20(0.25,2.25)
  rect 0.95x0.3 smd: 2(-1.25,1.75) 3(-1.25,1.25) 4(-1.25,0.75) 5(-1.25,0.25) 6(-1.25,-0.25) 7(-1.25,-0.75) 8(-1.25,-1.25) 9(-1.25,-1.75) 12(1.25,-1.75) 13(1.25,-1.25) 14(1.25,-0.75) 15(1.25,-0.25) 16(1.25,0.25) 17(1.25,0.75) 18(1.25,1.25) 19(1.25,1.75)
  rect 1.15x3.15 smd: 21(0,0)
HARWIN_M20-9960245
  rect 1.7x1.7 hole 1: 1(0,0)
  round 1.7 hole 1: 2(2.54,0)
INDC1005X60M
  rect 0.7x0.74 smd: 1(-0.52,0) 2(0.52,0)
INDC2012X105M
  rect 1.35x1.55 smd: 1(-1,0) 2(1,0)
INDC2016X100M
  rect 1.3x1.9 smd: 1(-1,0) 2(1,0)
INDM4242X200M
  rect 2.15x3.25 smd: 1(-1.9,0) 2(1.9,0)
JAE_DX07S024XJ1R1100
  round 0.5 hole 0.75 unplated: (-0.85,-0.66)
  round 0.5 hole 0.95x0.75 unplated: (6.35,-0.66)
  rect 0.3x1.1 smd: A1(0,0) A2(0.5,0) A3(1,0) A4(1.5,0) A5(2,0) A6(2.5,0) A7(3,0) A8(3.5,0) A9(4,0) A10(4.5,0) A11(5,0) A12(5.5,0)
  round 0.65 hole 0.4: B1(5.55,-1.31) B2(5.15,-2.01) B3(4.35,-2.01) B4(3.95,-1.31) B5(3.55,-2.01) B6(3.15,-1.31) B7(2.35,-1.31) B8(1.95,-2.01) B9(1.55,-1.31) B10(1.15,-2.01) B11(0.35,-2.01) B12(-0.05,-1.31)
  oval 1.1x2.1 hole 0.6x1.6: SH1(-1.85,-2.06) SH2(7.35,-2.06) SH3(-1.85,-5.06) SH4(7.35,-5.06)
JST_S2B-PH-K-S
  rect 1.4x1.4 hole 0.7: 1(0,0)
  round 1.4 hole 0.7: 2(2,0)
KEYSTONE_5000
  round 1.72 hole 1.02: 1(0,0)
LED_AAA3528LSEEZGKQBKS
  rect 1.2x0.9 smd: 1(1.4,-0.725) 2(-1.4,-0.725) 3(-1.4,0.725) 4(1.4,0.725)
LEDC2012X120M
  rect 1.15x1.55 smd: A(-1.1,0) K(1.1,0)
MODULE_LBEE5KL1DX-TEMP
  rect 0.5x0.25 smd: 1(-2.025,2.25) 2(-2.025,1.8) 3(-2.025,1.35) 4(-2.025,0.9) 5(-2.025,0.45) 6(-2.025,0) 7(-2.025,-0.45) 8(-2.025,-0.9) 9(-2.025,-1.35) 10(-2.025,-1.8) 11(-2.025,-2.25) 22(2.025,-2.25) 23(2.025,-1.8) 24(2.025,-1.35) 25(2.025,-0.9) 26(2.025,-0.45) 27(2.025,0) 28(2.025,0.45) 29(2.025,0.9) 30(2.025,1.35) 31(2.025,1.8) 32(2.025,2.25)
  rect 0.375x0.5 smd: 12(-2.087,-2.925) 21(2.087,-2.925) 33(2.087,2.925) 42(-2.087,2.925)
  rect 0.25x0.5 smd: 13(-1.575,-2.925) 14(-1.125,-2.925) 15(-0.675,-2.925) 16(-0.225,-2.925) 17(0.225,-2.925) 18(0.675,-2.925) 19(1.125,-2.925) 20(1.575,-2.925) 34(1.575,2.925) 35(1.125,2.925) 36(0.675,2.925) 37(0.225,2.925) 38(-0.225,2.925) 39(-0.675,2.925) 40(-1.125,2.925) 41(-1.575,2.925)
  custom 0.25x0.25 smd: 43(-0.75,1)
  rect 1x1 smd: 44(-0.75,-1) 45(0.75,1) 46(0.75,-1)
MOLEX_676433911
  rect 1.65x1.65 hole 0.95: 1(0,0)
  round 1.65 hole 0.95: 2(2.5,0) 3(4.5,0) 4(7,0)
  round 3 hole 2.3: 5(-3.07,-2.71) 6(10.07,-2.71)
MSOP65P490X110-8M
  rect 1.65x0.45 smd: 1(-2.3,0.975) 2(-2.3,0.325) 3(-2.3,-0.325) 4(-2.3,-0.975) 5(2.3,-0.975) 6(2.3,-0.325) 7(2.3,0.325) 8(2.3,0.975)
NET_TIE_COPPERTRACE
  rect 0.3x0.25 smd: 1(-0.275,0) 2(0.275,0)
OSCCC200X250X90-4M
  rect 1.45x1.25 smd: 1(-0.95,-0.8) 2(0.95,-0.8) 3(0.95,0.8) 4(-0.95,0.8)
OST_OSTVN02A150
  rect 2x2 hole 1.3: 1(0,0)
  round 2 hole 1.3: 2(2.54,0)
QFN40P140X180X55-10M
  rect 0.2x0.9 smd: 1(-0.2,-0.75) 2(0.2,-0.75) 6(0.2,0.75) 7(-0.2,0.75)
  rect 0.9x0.2 smd: 3(0.95,-0.4) 4(0.95,0) 5(0.95,0.4) 8(-0.95,0.4) 9(-0.95,0) 10(-0.95,-0.4)
QFN40P140X180X60-10M
  rect 0.9x0.2 smd: 1(-0.75,0.2) 2(-0.75,-0.2) 6(0.75,-0.2) 7(0.75,0.2)
  rect 0.2x0.9 smd: 3(-0.4,-0.95) 4(0,-0.95) 5(0.4,-0.95) 8(0.4,0.95) 9(0,0.95) 10(-0.4,0.95)
QFN40P800X800X100-69M
  round 1 smd: (-4.809,-4.809) (4.809,4.809)
  oval 0.95x0.2 smd: 1(-4,3.2) 2(-4,2.8) 3(-4,2.4) 4(-4,2) 5(-4,1.6) 6(-4,1.2) 7(-4,0.8) 8(-4,0.4) 9(-4,0) 10(-4,-0.4) 11(-4,-0.8) 12(-4,-1.2) 13(-4,-1.6) 14(-4,-2) 15(-4,-2.4) 16(-4,-2.8) 17(-4,-3.2) 35(4,-3.2) 36(4,-2.8) 37(4,-2.4) 38(4,-2) 39(4,-1.6) 40(4,-1.2) 41(4,-0.8) 42(4,-0.4) 43(4,0) 44(4,0.4) 45(4,0.8) 46(4,1.2) 47(4,1.6) 48(4,2) 49(4,2.4) 50(4,2.8) 51(4,3.2)
  oval 0.2x0.95 smd: 18(-3.2,-4) 19(-2.8,-4) 20(-2.4,-4) 21(-2,-4) 22(-1.6,-4) 23(-1.2,-4) 24(-0.8,-4) 25(-0.4,-4) 26(0,-4) 27(0.4,-4) 28(0.8,-4) 29(1.2,-4) 30(1.6,-4) 31(2,-4) 32(2.4,-4) 33(2.8,-4) 34(3.2,-4) 52(3.2,4) 53(2.8,4) 54(2.4,4) 55(2,4) 56(1.6,4) 57(1.2,4) 58(0.8,4) 59(0.4,4) 60(0,4) 61(-0.4,4) 62(-0.8,4) 63(-1.2,4) 64(-1.6,4) 65(-2,4) 66(-2.4,4) 67(-2.8,4) 68(-3.2,4)
  rect 5.8x5.8 smd: 69(0,0)
QFN50P250X300X100-15M_NOFID
  custom 0.062x0.062 smd: 1(-1.15,0.75) 2(-1.15,0.25) 3(-1.15,-0.25) 4(-1.15,-0.75) 5(-0.75,-1.4) 6(-0.25,-1.4) 8(0.75,-1.4) 12(0.75,1.4) 14(-0.25,1.4) 15(-0.75,1.4)
  custom 0.175x0.175 smd: 7(0.525,-1.4) 13(0.525,1.4)
  custom 0.088x0.088 smd: 9(0.775,-0.5) 10(0.6,0) 11(0.775,0.5)
QFN50P400X400X100-25M
  round 1 smd: (-2.834,2.834) (2.834,-2.834)
  custom 0.075x0.075 smd: 1(-2.05,1.25) 2(-2.05,0.75) 3(-2.05,0.25) 4(-2.05,-0.25) 5(-2.05,-0.75) 6(-2.05,-1.25) 7(-1.25,-2.05) 8(-0.75,-2.05) 9(-0.25,-2.05) 10(0.25,-2.05) 11(0.75,-2.05) 12(1.25,-2.05) 13(2.05,-1.25) 14(2.05,-0.75) 15(2.05,-0.25) 16(2.05,0.25) 17(2.05,0.75) 18(2.05,1.25) 19(1.25,2.05) 20(0.75,2.05) 21(0.25,2.05) 22(-0.25,2.05) 23(-0.75,2.05) 24(-1.25,2.05)
  rect 2.8x2.8 smd: EPAD(0,0)
QFN50P600X600X60-41M
  round 1 smd: (-3.809,-3.809) (3.809,3.809)
  oval 0.9x0.3 smd: 1(-3.05,2.25) 2(-3.05,1.75) 3(-3.05,1.25) 4(-3.05,0.75) 5(-3.05,0.25) 6(-3.05,-0.25) 7(-3.05,-0.75) 8(-3.05,-1.25) 9(-3.05,-1.75) 10(-3.05,-2.25) 21(3.05,-2.25) 22(3.05,-1.75) 23(3.05,-1.25) 24(3.05,-0.75) 25(3.05,-0.25) 26(3.05,0.25) 27(3.05,0.75) 28(3.05,1.25) 29(3.05,1.75) 30(3.05,2.25)
  oval 0.3x0.9 smd: 11(-2.25,-3.05) 12(-1.75,-3.05) 13(-1.25,-3.05) 14(-0.75,-3.05) 15(-0.25,-3.05) 16(0.25,-3.05) 17(0.75,-3.05) 18(1.25,-3.05) 19(1.75,-3.05) 20(2.25,-3.05) 31(2.25,3.05) 32(1.75,3.05) 33(1.25,3.05) 34(0.75,3.05) 35(0.25,3.05) 36(-0.25,3.05) 37(-0.75,3.05) 38(-1.25,3.05) 39(-1.75,3.05) 40(-2.25,3.05)
  rect 4.7x4.7 smd: 41(0,0)
RESC1005X40M
  rect 0.65x0.72 smd: 1(-0.54,0) 2(0.54,0)
RESC1005X40M_A
  rect 0.7x0.72 smd: 1(-0.51,0) 2(0.51,0)
RESC1005X40M_B
  rect 0.68x0.72 smd: 1(-0.52,0) 2(0.52,0)
RESC1608X55M_A
  rect 1.1x1.1 smd: 1(-0.9,0) 2(0.9,0)
RESC6432X120M
  rect 2.6x3.5 smd: 1(-2.5,0) 2(2.5,0)
RF_SW_MUR_MM8430-2610B
  rect 1x1 smd: G1(-1.5,1) G2(-1.5,-1) G3(1.5,-1) G4(1.5,1)
  rect 0.5x0.6 smd: I(0,1.35) O(0,-1.35)
SAMTEC_BCS-101-L-S-HE
  rect 1.45x1.45 hole 0.75: 1(0,0)
  round 1.45 hole 0.75: 2(0,7.87)
SAMTEC_FTSH-105-01-L-DV-K
  rect 0.737x2.794 smd: 1(0,0) 2(0,4.064) 3(1.27,0) 4(1.27,4.064) 5(2.54,0) 6(2.54,4.064) 7(3.81,0) 8(3.81,4.064) 9(5.08,0) 10(5.08,4.064)
SOD2513X120M_12_DI
  rect 1.1x0.5 smd: 1(-1.35,0) 2(1.35,0)
SOD2513X120M_DI
  rect 1.1x0.5 smd: A(1.35,0) K(-1.35,0)
SOD3715X145M
  rect 1.2x0.8 smd: A(-1.9,0) K(1.9,0)
SODFL1608X77M
  rect 0.61x0.787 smd: A(-0.838,0) K(0.838,0)
SODFL4725X110M
  rect 1.1x2.03 smd: A(2.26,0) K(-2.26,0)
SOIC127P600X175-8M
  rect 1.75x0.65 smd: 1(-2.8,1.905) 2(-2.8,0.635) 3(-2.8,-0.635) 4(-2.8,-1.905) 5(2.8,-1.905) 6(2.8,-0.635) 7(2.8,0.635) 8(2.8,1.905)
SOIC127P800X203-8M
  rect 1.951x0.65 smd: 1(-3.701,1.905) 2(-3.701,0.635) 3(-3.701,-0.635) 4(-3.701,-1.905) 5(3.701,-1.905) 6(3.701,-0.635) 7(3.701,0.635) 8(3.701,1.905)
SON50P300X300X100-11M_VS
  oval 0.9x0.3 smd: 1(-1.55,1) 2(-1.55,0.5) 3(-1.55,0) 4(-1.55,-0.5) 5(-1.55,-1) 6(1.55,-1) 7(1.55,-0.5) 8(1.55,0) 9(1.55,0.5) 10(1.55,1)
  rect 1.7x2.45 smd: EPAD(0,0)
SOT65P210X110-6M
  rect 1.1x0.45 smd: 1(-1.15,0.65) 2(-1.15,0) 3(-1.15,-0.65) 4(1.15,-0.65) 5(1.15,0) 6(1.15,0.65)
SOT92P240X110-3M
  rect 0.65x1.15 smd: 1(-0.915,-1.2) 2(0.915,-1.2) 3(0,1.2)
SOT95P230X110-3M
  rect 0.65x1.2 smd: 1(-0.95,-1.25) 2(0.95,-1.25) 3(0,1.25)
SOT95P237X111-3M_A
  rect 0.65x1.25 smd: 1(-0.95,-1.25) 2(0.95,-1.25) 3(0,1.25)
SOT95P275X140-5M
  rect 1.3x0.65 smd: 1(-1.45,0.95) 2(-1.45,0) 3(-1.45,-0.95) 4(1.45,-0.95) 5(1.45,0.95)
SOT95P280X145-5M
  rect 1.3x0.65 smd: 1(-1.4,0.95) 2(-1.4,0) 3(-1.4,-0.95) 4(1.4,-0.95) 5(1.4,0.95)
SOT95P285X140-5M
  rect 1.3x0.65 smd: 1(-1.4,0.95) 2(-1.4,0) 3(-1.4,-0.95) 4(1.4,-0.95) 5(1.4,0.95)
SULLINS_PBC08SAAN
  rect 1.85x1.85 hole 1.15: 1(0,0)
  round 1.85 hole 1.15: 2(2.54,0) 3(5.08,0) 4(7.62,0) 5(10.16,0) 6(12.7,0) 7(15.24,0) 8(17.78,0)
SULLINS_PBC10SAAN
  rect 1.85x1.85 hole 1.15: 1(0,0)
  round 1.85 hole 1.15: 2(2.54,0) 3(5.08,0) 4(7.62,0) 5(10.16,0) 6(12.7,0) 7(15.24,0) 8(17.78,0) 9(20.32,0) 10(22.86,0)
SULLINS_PPPC032LFBN-RC_FLIP
  rect 1.72x1.72 hole 1.02: 1(0,0)
  round 1.72 hole 1.02: 2(0,2.54) 3(2.54,0) 4(2.54,2.54) 5(5.08,0) 6(5.08,2.54)
SULLINS_PPPC042LFBN-RC_FLIP
  rect 1.72x1.72 hole 1.02: 1(0,-2.54)
  round 1.72 hole 1.02: 2(0,0) 3(2.54,-2.54) 4(2.54,0) 5(5.08,-2.54) 6(5.08,0) 7(7.62,-2.54) 8(7.62,0)
SULLINS_PPPC052LFBN-RC_FLIP
  rect 1.72x1.72 hole 1.02: 1(0,0)
  round 1.72 hole 1.02: 2(0,2.54) 3(2.54,0) 4(2.54,2.54) 5(5.08,0) 6(5.08,2.54) 7(7.62,0) 8(7.62,2.54) 9(10.16,0) 10(10.16,2.54)
SULLINS_PPPC061LGBN-RC_FLIP
  rect 1.72x1.72 hole 1.02: 1(0,0)
  round 1.72 hole 1.02: 2(-2.54,0) 3(-5.08,0) 4(-7.62,0) 5(-10.16,0) 6(-12.7,0)
SULLINS_PPPC081LFBN-RC
  rect 1.72x1.72 hole 1.02: 1(0,0)
  round 1.72 hole 1.02: 2(2.54,0) 3(5.08,0) 4(7.62,0) 5(10.16,0) 6(12.7,0) 7(15.24,0) 8(17.78,0)
SULLINS_PPPC082LFBN-R_FLIP
  rect 1.72x1.72 hole 1.02: 1(0,0)
  round 1.72 hole 1.02: 2(0,2.54) 3(2.54,0) 4(2.54,2.54) 5(5.08,0) 6(5.08,2.54) 7(7.62,0) 8(7.62,2.54) 9(10.16,0) 10(10.16,2.54) 11(12.7,0) 12(12.7,2.54) 13(15.24,0) 14(15.24,2.54) 15(17.78,0) 16(17.78,2.54)
SULLINS_PPPC101LFBN-RC
  rect 1.72x1.72 hole 1.02: 1(0,0)
  round 1.72 hole 1.02: 2(2.54,0) 3(5.08,0) 4(7.62,0) 5(10.16,0) 6(12.7,0) 7(15.24,0) 8(17.78,0) 9(20.32,0) 10(22.86,0)
SULLINS_PPPC102LFBN-R_FLIP
  rect 1.72x1.72 hole 1.02: 1(0,0)
  round 1.72 hole 1.02: 2(0,2.54) 3(2.54,0) 4(2.54,2.54) 5(5.08,0) 6(5.08,2.54) 7(7.62,0) 8(7.62,2.54) 9(10.16,0) 10(10.16,2.54) 11(12.7,0) 12(12.7,2.54) 13(15.24,0) 14(15.24,2.54) 15(17.78,0) 16(17.78,2.54) 17(20.32,0) 18(20.32,2.54) 19(22.86,0) 20(22.86,2.54)
SW_CL-SB-13B-01T
  round 0.5 hole 0.899 unplated: (-3,0) (5.001,0)
  rect 1.199x1.4 smd: 1(-4,2.2) 2(-1.999,-2.2) 3(1.999,-2.2) 4(4,2.2)
SW_EVQ-PE105K
  rect 2x1.6 smd: A(-2.7,0) B(2.7,0)
SW_JS202011JCQN
  rect 1x1.6 smd: 1(-2.5,-1.2) 2(0,-1.2) 3(2.5,-1.2) 5(-2.5,1.2) 6(0,1.2) 7(2.5,1.2)
SW_SKRPACE010
  rect 1.05x0.65 smd: 1(-2.075,1.075) 2(2.075,1.075) 3(-2.075,-1.075) 4(2.075,-1.075)
TDFN50P160X120X60-5M
  rect 0.8x0.3 smd: 1(-0.9,0.25) 2(-0.9,-0.25) 3(0.9,-0.25) 4(0.9,0.25)
  rect 0.55x0.9 smd: H(0,0)
TP50_12D_24BOT_MIL
  round 0.609 hole 0.305: 1(0,0)
TP102C
  round 1.016 smd: 1(0,0)
TP127D033
  round 1.27 hole 0.33: 1(0,0)
TSSOP65P212X110-5M
  rect 1.1x0.45 smd: 1(-1.15,0.65) 2(-1.15,0) 3(-1.15,-0.65) 4(1.15,-0.65) 5(1.15,0.65)
unnamed
  round 1.72 hole 1.02: 1(0,0)
unnamed#3
  round 1 smd: (0,0)
XTAL320X150X90N_ECS
  rect 1.1x1.9 smd: 1(-1.25,0) 2(1.25,0)
XTL-11-5X4-8MM_DAB
  rect 4.801x1.501 smd: 1(-4.6,0) 2(4.6,0)

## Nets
5V_OUT: C133.1 C134.1 C135.1 C136.1 C141.2 C142.1 D5.A(ANODE) D8.A(ANODE) R165.2 R171.1 U29.1(IN) U29.3(EN) U30.7(VOUT1) U30.8(VOUT2)
GND: C1.1 C2.1 C5.2 C7.2 C8.2 C10.2 C11.2 C12.2 C13.2 C14.2 C15.2 C16.1 C17.2 C18.2 C19.2 C20.2 C21.2 C22.2 C23.2 C24.2 C25.2 C26.2 C27.1 C28.2 C29.2 C30.1 C31.2 C32.2 C33.1 C34.2 C35.2 C36.2 C37.2 C38.2 C39.2 C40.2 C41.2 C42.2 C43.2 C44.1 C45.2 C46.2 C47.2 C48.2 C49.2 C50.2 C51.2 C52.2 C53.2 C54.2 C55.2 C56.1 C57.2 C58.2 C59.2 C60.2 C61.1 C62.1 C63.2 C64.2 C65.2 C66.2 C67.2 C68.2 C69.2 C70.2 C71.2 C72.2 C73.2 C74.1 C75.2 C76.1 C77.2 C78.1 C79.2 C80.1 C81.1 C82.1 C83.2 C85.2 C86.2 C87.2 C88.2 C89.2 C90.1 C91.2 C92.2 C93.2 C94.2 C95.2 C96.2 C97.2 C98.2 C99.2 C100.2 C101.2 C102.1 C103.2 C104.2 C105.2 C106.2 C107.2 C108.2 C109.2 C110.2 C111.2 C112.2 C113.2 C114.2 C115.2 C116.2 C117.2 C118.2 C119.1 C120.2 C121.2 C122.2 C123.2 C124.2 C125.2 C126.2 C127.2 C128.2 C129.2 C130.2 C131.2 C132.2 C133.2 C134.2 C135.2 C136.2 C137.2 C138.2 C139.2 C140.1 C141.1 C143.1 C144.1 C145.1 C146.1 C147.2 C148.1 D10.A(ANODE) J1.2 J1.3 J2.14 J3.7 J5.6 J6.16 J7.4 J9.1 J10.A1(GND_1) J10.A12(GND_2) J10.B1(GND_3) J10.B12(GND_4) J11.3 J11.5 J11.7 J11.9 J12.3 J12.5 J12.9 J12.15 J12.17 J12.19 J14.5 J15.2 J16.1 J19.7 J21.7 J25.2 J25.4 J25.6 J25.8 J25.10 J27.4(GND) J28.A1(GND_1) J28.A12(GND_2) J28.B1(GND_3) J28.B12(GND_4) J29.G1 J29.G2 J29.G3 J29.G4 L11.2 L12.2 LED1.K(CATHODE) LED2.K(CATHODE) LED3.K(CATHODE) LED4.K(CATHODE) Q3.1(G) R2.2 R3.1 R4.1 R9.2 R10.2 R14.1 R33.1 R42.1 R44.2 R46.1 R48.2 R65.2 R68.1 R69.2 R76.1 R78.2 R79.2 R84.1 R86.1 R87.2 R90.1 R94.1 R98.1 R100.2 R101.1 R105.2 R107.2 R119.1 R121.2 R125.1 R136.1 R140.1 R167.1 R168.1 R169.1 R170.1 R184.1 R185.1 R195.1 R198.1 R199.1 R204.1 SH1.1 SW1.A(2) SW3.3 SW3.4 SW4.3 SW4.4 SW5.2 TP8.1 TP12.1 TP20.1 TP28.1 TP30.1 TVS2.3 TVS4.A TVS5.1 U1.B12(VSS0) U1.C3(VSS1) U1.D4(VSS2) U1.D10(VSS3) U1.K4(VSS4) U1.K10(VSS5) U2.5(VSSB) U2.7(VBOOST) U2.8(VBAT) U2.9(VSSD#9) U2.25(VSSD#25) U2.43(VSSA) U2.45(VSSD#45) U2.58(VSSD#58) U2.63(P2[1]) U2.69(EPAD) U3.33(VSS) U3.41(EPAD) U4.B3(VSS) U5.4(VSS) U6.1(GND1) U6.12(GND_12) U6.19(GND_19) U6.21(GND_21) U6.29(GND_29) U6.32(GND(SR_PVSS) 32) U6.33(GND(SR_PVSS) 33) U6.35(GND_35) U6.40(GND40) U6.42(GND42) U6.43(GND43) U6.44(GND44) U6.45(GND45) U6.46(GND46) U7.2(GND) U7.H(PAD) U8.2(GND) U8.H(PAD) U9.2(GND) U10.2(GND) U11.2(GND) U12.3(GND) U14.3(GND) U15.2(GND) U16.3(GND) U16.8(O\E\) U17.10(GND) U18.2(GND) U19.20(AGND) U19.21(PGND#21) U19.22(PGND#22) U19.EPAD U20.3(GND) U21.2(COMP2) U22.3(GND) U23.2(GND) U23.H(PAD) U24.2(GND) U24.H(PAD) U25.9(GND) U26.2(GND) U26.H(PAD) U27.4(GND) U27.5(RW) U27.6(RL) U28.2(GND) U28.H(PAD) U29.2(GND) U29.H(PAD) U30.4(GND) U30.6(FB2) U30.10(PGND) U30.15(VSEL) U31.6(GND) U31.EPAD
GND_EARTH1: C48.1 J28.SH1 J28.SH2 J28.SH3 J28.SH4 R69.1 TVS1.A
GND_EARTH2: C58.1 J27.5(S1) J27.6(S2) R78.1
GND_EARTH3: C92.1 J10.SH1 J10.SH2 J10.SH3 J10.SH4 R121.1 TVS3.1
VBAT: C88.1 J15.1 U19.8(BAT#8) U19.9(BAT#9)
VBAT_PP: C52.1 C87.1 D1.A(ANODE) L8.2 U19.6(SYS#6) U19.7(SYS#7)
VBUS_DEV: C51.1 D3.A(ANODE) J28.A4(VBUS_1) J28.A9(VBUS_2) J28.B4(VBUS_3) J28.B9(VBUS_4) R101.2 TVS1.K U22.1(OE) U22.2(IN)
VBUS_DISCHARGE: R127.2 U3.32(VBUS_DISCHARGE)
VBUS_HOST: C57.1 C66.1 J27.1(VBUS) U15.1(OUT)
VBUS_P_CTRL0: R143.1 R144.2 U3.2(VBUS_P_CTRL0)
VBUS_P_CTRL1: R137.1 R138.1 U3.1(VBUS_P_CTRL1)
VBUS_TC: C74.2 C78.2 C89.1 C102.2 D6.A(ANODE) J10.A4(VBUS_1) J10.A9(VBUS_2) J10.B4(VBUS_3) J10.B9(VBUS_4) Q1.7(D2#7) Q1.8(D2#8) R7.1 R26.1 R118.1 R127.1 R167.2 TVS3.2 U13.5(VS_1) U13.6(VS_2) U13.7(VS_3) U13.8(VS_4)
VBUS_TC_MON: C10.1 R3.2 R7.2 U3.24(P2.5)
VCC_1V8: C76.2 C81.2 R103.2 U14.5(VCC) U18.5(OUT) U20.5(VCC)
VCC_3V3: C13.1 C16.2 C41.1 C65.1 C109.1 C110.1 C111.1 L3.1 R15.1 R41.2 R57.1 TP9.1 U4.B4(VCC) U7.3(IN) U9.5(OUT) U16.9(VCC) U24.4(EN) U28.1(IN) U28.3(EN)
VCC_5V: C39.1 C43.1 C46.1 C47.1 C61.2 C62.2 C63.1 C64.1 C90.2 C131.1 D2.A(ANODE) D3.K(CATHODE) D4.K(CATHODE) D5.K(CATHODE) R1.2 R5.2 R6.2 R80.2 R92.2 R97.1 R124.1 R197.2 TP27.1 U9.1(IN) U10.1(IN) U12.5(VCC) U15.5(IN) U18.1(VIN) U18.3(CONTROL) U19.18(IN#18) U19.19(IN#19) U21.5(COMP1) U23.3(IN) U27.8(VCC)
VCC_IN: C137.1 C138.1 C139.1 C140.2 D6.K(CATHODE) D7.K(CATHODE) R163.2 R164.2 U30.12(VIN1) U30.13(VIN2)
VCC_IO_FLASH: C94.1 C95.1 R134.1 U4.E4(VIO/RFU) U24.1(OUT)
VCC_VAR: C45.1 R49.1 R50.2 U8.1(IN) U10.5(OUT)
VCCD: C93.1 R129.2 TP6.1 U1.A2(VCCD)
VDD_NS: C18.1 C24.1 L4.2 TP3.1 U1.J1(VDD_NS)
VDDA: C35.1 C36.1 C37.1 C38.1 L6.2 TP26.1 U1.A12(VDDA) U1.A13(VDDIOA)
VDDD: C20.1 C26.1 C100.1 C101.1 C104.1 C105.1 C114.1 C117.1 L5.2 R91.1 R147.1 SW7.1 TP2.1 U1.A1(VDDD) U1.C4(VDDIO0) U1.K12(VDDIO1) U1.L4(VDDIOR)
VDDUSB: C21.1 C22.1 R15.2 TP10.1 U1.M1(VDDUSB) U7.1(OUT)
VIN: C144.2 C145.2 C148.2 D7.A(ANODE) J1.1 J9.2 R16.1 R170.2 TVS5.2 U31.1(VIN#1) U31.2(VIN#2)
VIN_MON: C15.1 R14.2 R16.2 U3.25(P2.6)
ANT: C4.2 L11.1 U6.41(ANT)
BT_DEV_WAKE_P4_0: TP35.1 U1.L7(P4_0) U6.39(BT_DEV_WAKE)
BT_GPIO_3: TP22.1 U6.6(BT_GPIO_3)
BT_GPIO_4: TP23.1 U6.7(BT_GPIO_4)
BT_GPIO_5: TP17.1 U6.13(BT_GPIO_5)
BT_HOST_WAKE_P3_5: TP31.1 U1.N6(P3_5) U6.38(BT_HOST_WAKE)
BT_I2S_DO: TP18.1 U6.16(BT_I2S_DO)
BT_PCM_CLK: TP15.1 U6.11(BT_PCM_CLK)
BT_PCM_IN: TP13.1 U6.9(BT_PCM_IN)
BT_PCM_OUT: TP14.1 U6.10(BT_PCM_OUT)
BT_PCM_SYNC: TP24.1 U6.8(BT_PCM_SYNC)
